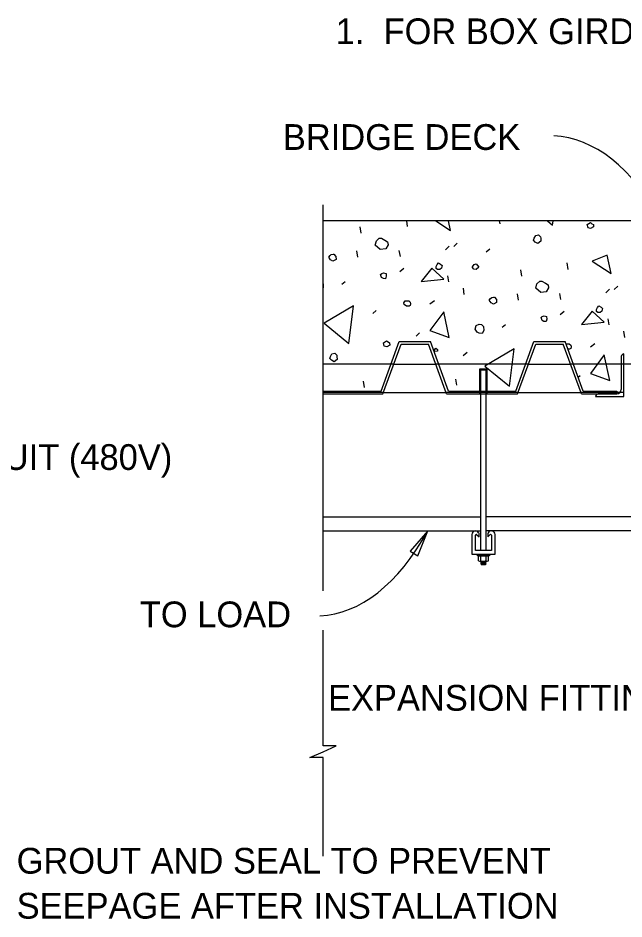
# Model space of a CAD drawing. Extents: x -1660015.2 to -1659984.9, y 2580594.2 to 2580616.7.
# Drawn here: x -1659994.44 to -1659990.89, y 2580599.96 to 2580605.25 of the extents above; entities that cross this region are included whole.
import ezdxf

# ---------------------------------------------------------------- set-up
doc = ezdxf.new("R2010")
doc.units = 0
for name, color, linetype in [('Default', 7, 'Continuous'), ('Miscellaneous', 7, 'Continuous'), ('Miscellaneous3', 7, 'Continuous'), ('PlotBorder_dp', 7, 'Continuous'), ('SheetLines_dp', 7, 'Continuous'), ('SteelGirder', 7, 'Continuous')]:
    doc.layers.add(name, color=color, linetype=linetype)

msp = doc.modelspace()

# ---------------------------------------------------------------- linework, layer by layer
at = {"layer": 'Default'}
for p, q in [((-1659992.2395, 2580603.2147), (-1659992.6544, 2580603.2147)), ((-1659991.4491, 2580603.2147), (-1659991.9926, 2580603.2147)), ((-1659989.3053, 2580603.2147), (-1659991.2021, 2580603.2147)), ((-1659992.3002, 2580603.048), (-1659992.6544, 2580603.048)), ((-1659991.5097, 2580603.048), (-1659991.9319, 2580603.048)), ((-1659990.8887, 2580603.048), (-1659991.1415, 2580603.048)), ((-1659992.6544, 2580602.3186), (-1659991.7286, 2580602.3186)), ((-1659989.6715, 2580602.3186), (-1659991.6974, 2580602.3186)), ((-1659992.6544, 2580602.2353), (-1659991.7286, 2580602.2353)), ((-1659991.7807, 2580602.2145), (-1659991.7807, 2580602.0999)), ((-1659991.7599, 2580602.1207), (-1659991.7599, 2580602.2097)), ((-1659991.751, 2580602.2134), (-1659991.7391, 2580602.2015)), ((-1659991.7391, 2580602.2194), (-1659991.7412, 2580602.2237)), ((-1659991.7391, 2580602.2015), (-1659991.7391, 2580602.2194)), ((-1659989.6716, 2580602.2353), (-1659991.6974, 2580602.2353)), ((-1659991.6848, 2580602.2237), (-1659991.6869, 2580602.2194)), ((-1659991.6869, 2580602.2194), (-1659991.6869, 2580602.2015)), ((-1659991.6869, 2580602.2015), (-1659991.675, 2580602.2134)), ((-1659991.6661, 2580602.2097), (-1659991.6661, 2580602.1207)), ((-1659991.6453, 2580602.0999), (-1659991.6453, 2580602.2145)), ((-1659991.7807, 2580602.0999), (-1659991.6453, 2580602.0999)), ((-1659991.6661, 2580602.1207), (-1659991.7599, 2580602.1207))]:
    msp.add_line(p, q, dxfattribs=at)
for centre, radius, start, end in [((-1659991.7599, 2580602.2145), 0.0208, 26.1794, 179.9999), ((-1659991.6661, 2580602.2145), 0.0208, 0.0001, 153.8206), ((-1659991.7547, 2580602.2097), 0.0052, 45, 180), ((-1659991.6713, 2580602.2097), 0.0052, 360, 135)]:
    msp.add_arc(centre, radius, start, end, dxfattribs=at)
at = {"layer": 'Miscellaneous'}
for p, q in [((-1659992.1582, 2580604.0233), (-1659992.1629, 2580604.056)), ((-1659991.6158, 2580604.0385), (-1659991.6189, 2580604.056)), ((-1659992.4306, 2580603.9824), (-1659992.436, 2580604.0201)), ((-1659992.4499, 2580603.8427), (-1659992.4554, 2580603.8804)), ((-1659992.2006, 2580603.8458), (-1659992.2067, 2580603.881)), ((-1659991.9152, 2580603.9065), (-1659991.9362, 2580603.8862)), ((-1659991.8664, 2580603.9244), (-1659991.8874, 2580603.9042)), ((-1659991.6766, 2580603.8891), (-1659991.6969, 2580603.8713)), ((-1659992.1806, 2580603.7757), (-1659992.204, 2580603.7561)), ((-1659991.2165, 2580603.771), (-1659991.2219, 2580603.8087)), ((-1659991.9169, 2580603.6973), (-1659991.923, 2580603.7326)), ((-1659991.4888, 2580603.7301), (-1659991.4943, 2580603.7678)), ((-1659992.5252, 2580603.6972), (-1659992.5448, 2580603.6818)), ((-1659990.9246, 2580603.6721), (-1659990.9456, 2580603.6518)), ((-1659991.8254, 2580603.6236), (-1659991.8308, 2580603.6613)), ((-1659991.5082, 2580603.5903), (-1659991.5136, 2580603.628)), ((-1659991.2589, 2580603.5934), (-1659991.2649, 2580603.6287)), ((-1659990.9734, 2580603.6541), (-1659990.9944, 2580603.6339)), ((-1659992.0013, 2580603.5853), (-1659992.0271, 2580603.5663)), ((-1659992.3424, 2580603.5292), (-1659992.3627, 2580603.5113)), ((-1659991.2388, 2580603.5233), (-1659991.2622, 2580603.5037)), ((-1659990.9751, 2580603.4449), (-1659990.9812, 2580603.4802)), ((-1659991.5834, 2580603.4449), (-1659991.603, 2580603.4294)), ((-1659990.8836, 2580603.3712), (-1659990.889, 2580603.4089)), ((-1659992.3139, 2580603.0559), (-1659992.2077, 2580603.3477)), ((-1659992.2077, 2580603.3477), (-1659992.0244, 2580603.3477)), ((-1659992.0875, 2580603.3988), (-1659992.1084, 2580603.3785)), ((-1659991.9182, 2580603.0559), (-1659992.0244, 2580603.3477)), ((-1659991.5234, 2580603.0559), (-1659991.4172, 2580603.3477)), ((-1659991.4172, 2580603.3477), (-1659991.2339, 2580603.3477)), ((-1659991.1278, 2580603.0559), (-1659991.2339, 2580603.3477)), ((-1659992.303, 2580603.0403), (-1659992.1968, 2580603.3321)), ((-1659992.1968, 2580603.3321), (-1659992.0353, 2580603.3321)), ((-1659991.9291, 2580603.0403), (-1659992.0353, 2580603.3321)), ((-1659991.5125, 2580603.0403), (-1659991.4063, 2580603.3321)), ((-1659991.4063, 2580603.3321), (-1659991.2449, 2580603.3321)), ((-1659991.1387, 2580603.0403), (-1659991.2449, 2580603.3321)), ((-1659991.0595, 2580603.3329), (-1659991.0853, 2580603.314)), ((-1659991.8081, 2580603.2825), (-1659991.8314, 2580603.2629)), ((-1659990.9043, 2580603.2591), (-1659990.9043, 2580603.0664)), ((-1659990.8887, 2580603.0247), (-1659990.8887, 2580603.2747)), ((-1659991.1457, 2580603.1464), (-1659991.1568, 2580603.1357)), ((-1659992.4119, 2580603.0767), (-1659992.4173, 2580603.1144)), ((-1659991.8695, 2580603.0919), (-1659991.8756, 2580603.1271)), ((-1659992.6544, 2580603.0559), (-1659992.3139, 2580603.0559)), ((-1659992.6544, 2580603.0403), (-1659992.303, 2580603.0403)), ((-1659991.9291, 2580603.0403), (-1659991.5125, 2580603.0403)), ((-1659991.9182, 2580603.0559), (-1659991.5234, 2580603.0559)), ((-1659991.1387, 2580603.0403), (-1659990.9304, 2580603.0403)), ((-1659991.1278, 2580603.0559), (-1659990.9304, 2580603.0559)), ((-1659990.9304, 2580603.0403), (-1659991.0397, 2580603.0403)), ((-1659990.9304, 2580603.0559), (-1659990.9304, 2580603.0403)), ((-1659991.0554, 2580603.0247), (-1659990.8887, 2580603.0247))]:
    msp.add_line(p, q, dxfattribs=at)
for points in [[(-1659991.9932, 2580604.056), (-1659991.9058, 2580603.9997)], [(-1659991.9058, 2580603.9997), (-1659991.9179, 2580604.056)], [(-1659991.3377, 2580604.056), (-1659991.3073, 2580604.0309)], [(-1659991.3073, 2580604.0309), (-1659991.3041, 2580604.056)], [(-1659991.0667, 2580604.0208), (-1659991.0851, 2580604.0101), (-1659991.0996, 2580604.014), (-1659991.1047, 2580604.0335), (-1659991.0857, 2580604.0465), (-1659991.0773, 2580604.0391), (-1659991.0683, 2580604.0341), (-1659991.0667, 2580604.0208), (-1659991.0654, 2580604.0256)], [(-1659992.2729, 2580603.9143), (-1659992.2866, 2580603.8921), (-1659992.3188, 2580603.8878), (-1659992.3481, 2580603.9137), (-1659992.3416, 2580603.9379), (-1659992.3244, 2580603.954), (-1659992.3116, 2580603.9532), (-1659992.2912, 2580603.9425), (-1659992.2756, 2580603.9331), (-1659992.2729, 2580603.9143)], [(-1659991.3771, 2580603.9538), (-1659991.3768, 2580603.9356), (-1659991.3934, 2580603.9219), (-1659991.409, 2580603.9313), (-1659991.4192, 2580603.9418), (-1659991.4159, 2580603.9539), (-1659991.4066, 2580603.9695), (-1659991.3901, 2580603.9728), (-1659991.3776, 2580603.9617), (-1659991.3771, 2580603.9538)], [(-1659992.5784, 2580603.8461), (-1659992.5781, 2580603.8279), (-1659992.5959, 2580603.8197), (-1659992.6097, 2580603.826), (-1659992.621, 2580603.8419), (-1659992.6129, 2580603.8527), (-1659992.6061, 2580603.8587), (-1659992.5952, 2580603.8609), (-1659992.5903, 2580603.8596), (-1659992.5784, 2580603.8461)], [(-1659990.964, 2580603.7473), (-1659990.987, 2580603.8545), (-1659991.0744, 2580603.8183), (-1659990.964, 2580603.7473)], [(-1659991.9464, 2580603.7129), (-1659992.0168, 2580603.7784), (-1659992.0794, 2580603.6994), (-1659991.9464, 2580603.7129)], [(-1659991.9598, 2580603.7787), (-1659991.9696, 2580603.7709), (-1659991.983, 2580603.7693), (-1659991.9914, 2580603.7768), (-1659991.9912, 2580603.7871), (-1659991.9856, 2580603.7985), (-1659991.9775, 2580603.8093), (-1659991.9643, 2580603.8006), (-1659991.9559, 2580603.7931), (-1659991.9598, 2580603.7787)], [(-1659991.7408, 2580603.7847), (-1659991.755, 2580603.7704), (-1659991.7701, 2580603.7718), (-1659991.7778, 2580603.7817), (-1659991.7765, 2580603.7865), (-1659991.7678, 2580603.7997), (-1659991.7562, 2580603.8043), (-1659991.7485, 2580603.7945), (-1659991.7408, 2580603.7847)], [(-1659992.2832, 2580603.7307), (-1659992.2871, 2580603.7162), (-1659992.2998, 2580603.7171), (-1659992.3113, 2580603.7227), (-1659992.317, 2580603.7398), (-1659992.3103, 2580603.7457), (-1659992.2987, 2580603.7504), (-1659992.2842, 2580603.7465), (-1659992.2832, 2580603.7307)], [(-1659992.6544, 2580603.6867), (-1659992.6531, 2580603.6642), (-1659992.6544, 2580603.6617)], [(-1659991.3311, 2580603.662), (-1659991.3448, 2580603.6397), (-1659991.377, 2580603.6354), (-1659991.4063, 2580603.6614), (-1659991.3998, 2580603.6855), (-1659991.3826, 2580603.7016), (-1659991.3699, 2580603.7008), (-1659991.3494, 2580603.6902), (-1659991.3338, 2580603.6808), (-1659991.3311, 2580603.662)], [(-1659992.143, 2580603.5586), (-1659992.1491, 2580603.555), (-1659992.1649, 2580603.5541), (-1659992.1775, 2580603.5652), (-1659992.1804, 2580603.5738), (-1659992.1716, 2580603.5869), (-1659992.151, 2580603.5866), (-1659992.1427, 2580603.5792), (-1659992.1404, 2580603.5682), (-1659992.143, 2580603.5586)], [(-1659991.6367, 2580603.5937), (-1659991.6364, 2580603.5755), (-1659991.6541, 2580603.5673), (-1659991.6679, 2580603.5736), (-1659991.6792, 2580603.5896), (-1659991.6711, 2580603.6004), (-1659991.6643, 2580603.6063), (-1659991.6534, 2580603.6086), (-1659991.6486, 2580603.6073), (-1659991.6367, 2580603.5937)], [(-1659992.5027, 2580603.3366), (-1659992.4748, 2580603.5569), (-1659992.6469, 2580603.4555), (-1659992.5027, 2580603.3366)], [(-1659991.9139, 2580603.3704), (-1659991.9459, 2580603.5213), (-1659992.0272, 2580603.4111), (-1659991.9139, 2580603.3704)], [(-1659991.0046, 2580603.4606), (-1659991.075, 2580603.5261), (-1659991.1376, 2580603.4471), (-1659991.0046, 2580603.4606)], [(-1659991.018, 2580603.5263), (-1659991.0279, 2580603.5186), (-1659991.0412, 2580603.517), (-1659991.0496, 2580603.5244), (-1659991.0494, 2580603.5347), (-1659991.0438, 2580603.5461), (-1659991.0357, 2580603.5569), (-1659991.0225, 2580603.5482), (-1659991.0141, 2580603.5408), (-1659991.018, 2580603.5263)], [(-1659991.3415, 2580603.4784), (-1659991.3453, 2580603.4639), (-1659991.3581, 2580603.4647), (-1659991.3695, 2580603.4704), (-1659991.3753, 2580603.4874), (-1659991.3685, 2580603.4934), (-1659991.3569, 2580603.498), (-1659991.3424, 2580603.4942), (-1659991.3415, 2580603.4784)], [(-1659991.7127, 2580603.4355), (-1659991.7113, 2580603.4118), (-1659991.7213, 2580603.3938), (-1659991.7388, 2580603.3959), (-1659991.7503, 2580603.4016), (-1659991.7609, 2580603.4199), (-1659991.755, 2580603.4417), (-1659991.7373, 2580603.4499), (-1659991.7253, 2580603.4466), (-1659991.7127, 2580603.4355)], [(-1659992.2621, 2580603.3265), (-1659992.2805, 2580603.3159), (-1659992.295, 2580603.3198), (-1659992.3001, 2580603.3393), (-1659992.2811, 2580603.3523), (-1659992.2727, 2580603.3449), (-1659992.2637, 2580603.3399), (-1659992.2621, 2580603.3265), (-1659992.2608, 2580603.3313)], [(-1659992.003, 2580603.289), (-1659992.0006, 2580603.2978), (-1659991.9926, 2580603.3086), (-1659991.9818, 2580603.3006), (-1659991.982, 2580603.2902)], [(-1659991.5609, 2580603.0843), (-1659991.533, 2580603.3045), (-1659991.7051, 2580603.2031), (-1659991.5609, 2580603.0843)], [(-1659991.2292, 2580603.3346), (-1659991.2093, 2580603.3343), (-1659991.2009, 2580603.3268), (-1659991.1986, 2580603.3159), (-1659991.2012, 2580603.3062)], [(-1659991.2012, 2580603.3062), (-1659991.2074, 2580603.3027), (-1659991.2173, 2580603.3021)], [(-1659992.5725, 2580603.2596), (-1659992.5722, 2580603.2414), (-1659992.5888, 2580603.2277), (-1659992.6045, 2580603.237), (-1659992.6146, 2580603.2475), (-1659992.6114, 2580603.2596), (-1659992.602, 2580603.2752), (-1659992.5856, 2580603.2786), (-1659992.573, 2580603.2674), (-1659992.5725, 2580603.2596)], [(-1659991.982, 2580603.2902), (-1659992.0027, 2580603.2882)], [(-1659990.9721, 2580603.118), (-1659991.0042, 2580603.2689), (-1659991.0855, 2580603.1587), (-1659990.9721, 2580603.118)], [(-1659991.051, 2580603.0559), (-1659991.0508, 2580603.0563), (-1659991.0504, 2580603.0559)]]:
    msp.add_lwpolyline(points, dxfattribs=at)
for centre, radius, start, end in [((-1659990.8887, 2580603.2591), 0.0156, 90.0047, 180.0047), ((-1659991.0397, 2580603.0247), 0.0156, 90.0047, 180.0047), ((-1659990.9304, 2580603.0664), 0.026, 270.0047, 0.0047)]:
    msp.add_arc(centre, radius, start, end, dxfattribs=at)
at = {"layer": 'Miscellaneous3'}
msp.add_line((-1659989.1387, 2580604.056), (-1659992.6544, 2580604.056), dxfattribs=at)
at = {"layer": 'SheetLines_dp'}
for points in [[(-1659992.6544, 2580601.8829), (-1659992.6544, 2580604.1496)], [(-1659992.6544, 2580600.3268), (-1659992.6544, 2580600.9057), (-1659992.7319, 2580600.9057), (-1659992.6544, 2580600.9395), (-1659992.5769, 2580600.9732), (-1659992.6544, 2580600.9732), (-1659992.6544, 2580601.6522)]]:
    msp.add_lwpolyline(points, dxfattribs=at)
msp.add_lwpolyline([(-1659992.0391, 2580602.2354), (-1659992.1436, 2580602.1163), (-1659992.0985, 2580602.0885)], close=True, dxfattribs=at)
for centre, major_axis, start_param, end_param in [((-1659991.4118, 2580602.1871), (-0.1111, -2.3674), 2.502126, 3.141581), ((-1659992.7842, 2580604.1042), (-0.1111, 2.3674), 3.141604, 3.781059)]:
    msp.add_ellipse(centre, major_axis=major_axis, ratio=0.464296, start_param=start_param, end_param=end_param, dxfattribs=at)
at = {"layer": 'SteelGirder'}
for p, q in [((-1659992.2395, 2580603.2147), (-1659991.9926, 2580603.2147)), ((-1659991.4491, 2580603.2147), (-1659991.2021, 2580603.2147)), ((-1659991.7338, 2580603.1861), (-1659991.6922, 2580603.1861)), ((-1659991.7338, 2580603.0403), (-1659991.7338, 2580603.1861)), ((-1659991.7286, 2580602.1207), (-1659991.7286, 2580603.1809)), ((-1659991.7286, 2580603.1809), (-1659991.6974, 2580603.1809)), ((-1659991.6974, 2580602.1207), (-1659991.6974, 2580603.1809)), ((-1659991.6922, 2580603.0403), (-1659991.6922, 2580603.1861)), ((-1659992.3002, 2580603.048), (-1659991.9319, 2580603.048)), ((-1659991.5097, 2580603.048), (-1659991.1415, 2580603.048)), ((-1659991.7431, 2580602.0604), (-1659991.7431, 2580602.0888)), ((-1659991.7431, 2580602.0888), (-1659991.6829, 2580602.0888)), ((-1659991.7281, 2580602.0604), (-1659991.7281, 2580602.0888)), ((-1659991.698, 2580602.0604), (-1659991.698, 2580602.0888)), ((-1659991.6829, 2580602.0604), (-1659991.6829, 2580602.0888)), ((-1659991.7356, 2580602.0582), (-1659991.6905, 2580602.0582)), ((-1659991.7287, 2580602.0576), (-1659991.7221, 2580602.0582)), ((-1659991.7287, 2580602.0576), (-1659991.7277, 2580602.0582)), ((-1659991.7234, 2580602.0554), (-1659991.7287, 2580602.0576)), ((-1659991.7287, 2580602.0524), (-1659991.7234, 2580602.0554)), ((-1659991.7287, 2580602.0524), (-1659991.6975, 2580602.0551)), ((-1659991.7234, 2580602.0502), (-1659991.7287, 2580602.0524)), ((-1659991.7287, 2580602.0472), (-1659991.7234, 2580602.0502)), ((-1659991.7287, 2580602.0472), (-1659991.6975, 2580602.0499)), ((-1659991.7234, 2580602.0451), (-1659991.7287, 2580602.0472)), ((-1659991.7287, 2580602.042), (-1659991.7234, 2580602.0451)), ((-1659991.7287, 2580602.042), (-1659991.6975, 2580602.0447)), ((-1659991.7234, 2580602.0398), (-1659991.7287, 2580602.042)), ((-1659991.7269, 2580602.0379), (-1659991.7234, 2580602.0398)), ((-1659991.7269, 2580602.0379), (-1659991.7003, 2580602.0379)), ((-1659991.7168, 2580602.0379), (-1659991.6975, 2580602.0395)), ((-1659991.7027, 2580602.0572), (-1659991.7011, 2580602.0582)), ((-1659991.6975, 2580602.0551), (-1659991.7027, 2580602.0572)), ((-1659991.7027, 2580602.052), (-1659991.6975, 2580602.0551)), ((-1659991.6975, 2580602.0499), (-1659991.7027, 2580602.052)), ((-1659991.7027, 2580602.0469), (-1659991.6975, 2580602.0499)), ((-1659991.6975, 2580602.0447), (-1659991.7027, 2580602.0469)), ((-1659991.7027, 2580602.0417), (-1659991.6975, 2580602.0447)), ((-1659991.6975, 2580602.0395), (-1659991.7027, 2580602.0417)), ((-1659991.7003, 2580602.0379), (-1659991.6975, 2580602.0395))]:
    msp.add_line(p, q, dxfattribs=at)
msp.add_lwpolyline([(-1659991.6777, 2580602.0999), (-1659991.6777, 2580602.0888), (-1659991.7483, 2580602.0888), (-1659991.7483, 2580602.0999)], close=True, dxfattribs=at)
for centre, radius, start, end in [((-1659991.7356, 2580602.072), 0.0138, 236.9791, 303.0209), ((-1659991.713, 2580602.11), 0.0519, 253.1396, 286.8604), ((-1659991.6905, 2580602.072), 0.0138, 236.9791, 303.0209)]:
    msp.add_arc(centre, radius, start, end, dxfattribs=at)

# ---------------------------------------------------------------- texts
at = {"layer": 'PlotBorder_dp'}
for s, p in [('BRIDGE DECK', (-1659992.89, 2580604.4721)), ('CONDUIT (480V)', (-1659995.1227, 2580602.5934)), ('TO LOAD', (-1659993.7295, 2580601.67)), ('EXPANSION FITTING', (-1659992.625, 2580601.1801))]:
    msp.add_text(s, height=0.1512, dxfattribs=at).set_placement(p)
at = {"layer": 'SheetLines_dp'}
for s, p in [('1.  FOR BOX GIRDER MAINTENANCE LIGHTING NOTES SEE SHEET 1.', (-1659992.5804, 2580605.0929)), ('GROUT AND SEAL TO PREVENT ', (-1659994.4521, 2580600.2236)), ('SEEPAGE AFTER INSTALLATION ', (-1659994.4521, 2580599.9596))]:
    msp.add_text(s, height=0.1512, dxfattribs=at).set_placement(p)

doc.saveas('drawing.dxf')
